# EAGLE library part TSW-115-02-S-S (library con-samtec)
THROUGH-HOLE .025" SQ POST HEADER Source: Samtec TSW.pdf
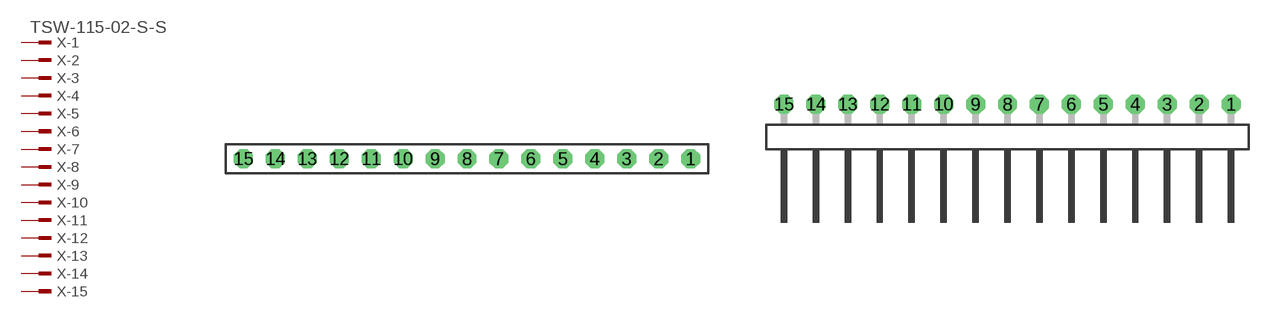
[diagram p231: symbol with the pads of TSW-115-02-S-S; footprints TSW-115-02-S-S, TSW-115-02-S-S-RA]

Designator prefix X; gates -1=MPINV -2=MPIN -3=MPIN -4=MPIN -5=MPIN -6=MPIN -7=MPIN -8=MPIN -9=MPIN -10=MPIN -11=MPIN -12=MPIN -13=MPIN -14=MPIN -15=MPIN

## TSW-115-02-S-S (OC_FARNELL: unknown; OC_NEWARK: unknown)  [TSW-115-02-S-S]
1  -1:1  pas
2  -2:1  pas
3  -3:1  pas
4  -4:1  pas
5  -5:1  pas
6  -6:1  pas
7  -7:1  pas
8  -8:1  pas
9  -9:1  pas
10  -10:1  pas
11  -11:1  pas
12  -12:1  pas
13  -13:1  pas
14  -14:1  pas
15  -15:1  pas

## TSW-115-02-S-S-RA (OC_FARNELL: unknown; OC_NEWARK: unknown)  [TSW-115-02-S-S-RA]
Pads as for TSW-115-02-S-S

## Footprint TSW-115-02-S-S (pad centres in mm)
THROUGH-HOLE .025" SQ POST HEADER Source: Samtec TSW.pdf
drill 1 pad 1.5 octagon: 1 17.78,0; 2 15.24,0; 3 12.7,0; 4 10.16,0; 5 7.62,0; 6 5.08,0; 7 2.54,0; 8 0,0; 9 -2.54,0; 10 -5.08,0; 11 -7.62,0; 12 -10.16,0; 13 -12.7,0; 14 -15.24,0; 15 -17.78,0

## Footprint TSW-115-02-S-S-RA (pad centres in mm)
THROUGH-HOLE .025" SQ POST HEADER Source: Samtec TSW.pdf
drill 1 pad 1.5 octagon: 1 17.78,1.524; 2 15.24,1.524; 3 12.7,1.524; 4 10.16,1.524; 5 7.62,1.524; 6 5.08,1.524; 7 2.54,1.524; 8 0,1.524; 9 -2.54,1.524; 10 -5.08,1.524; 11 -7.62,1.524; 12 -10.16,1.524; 13 -12.7,1.524; 14 -15.24,1.524; 15 -17.78,1.524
